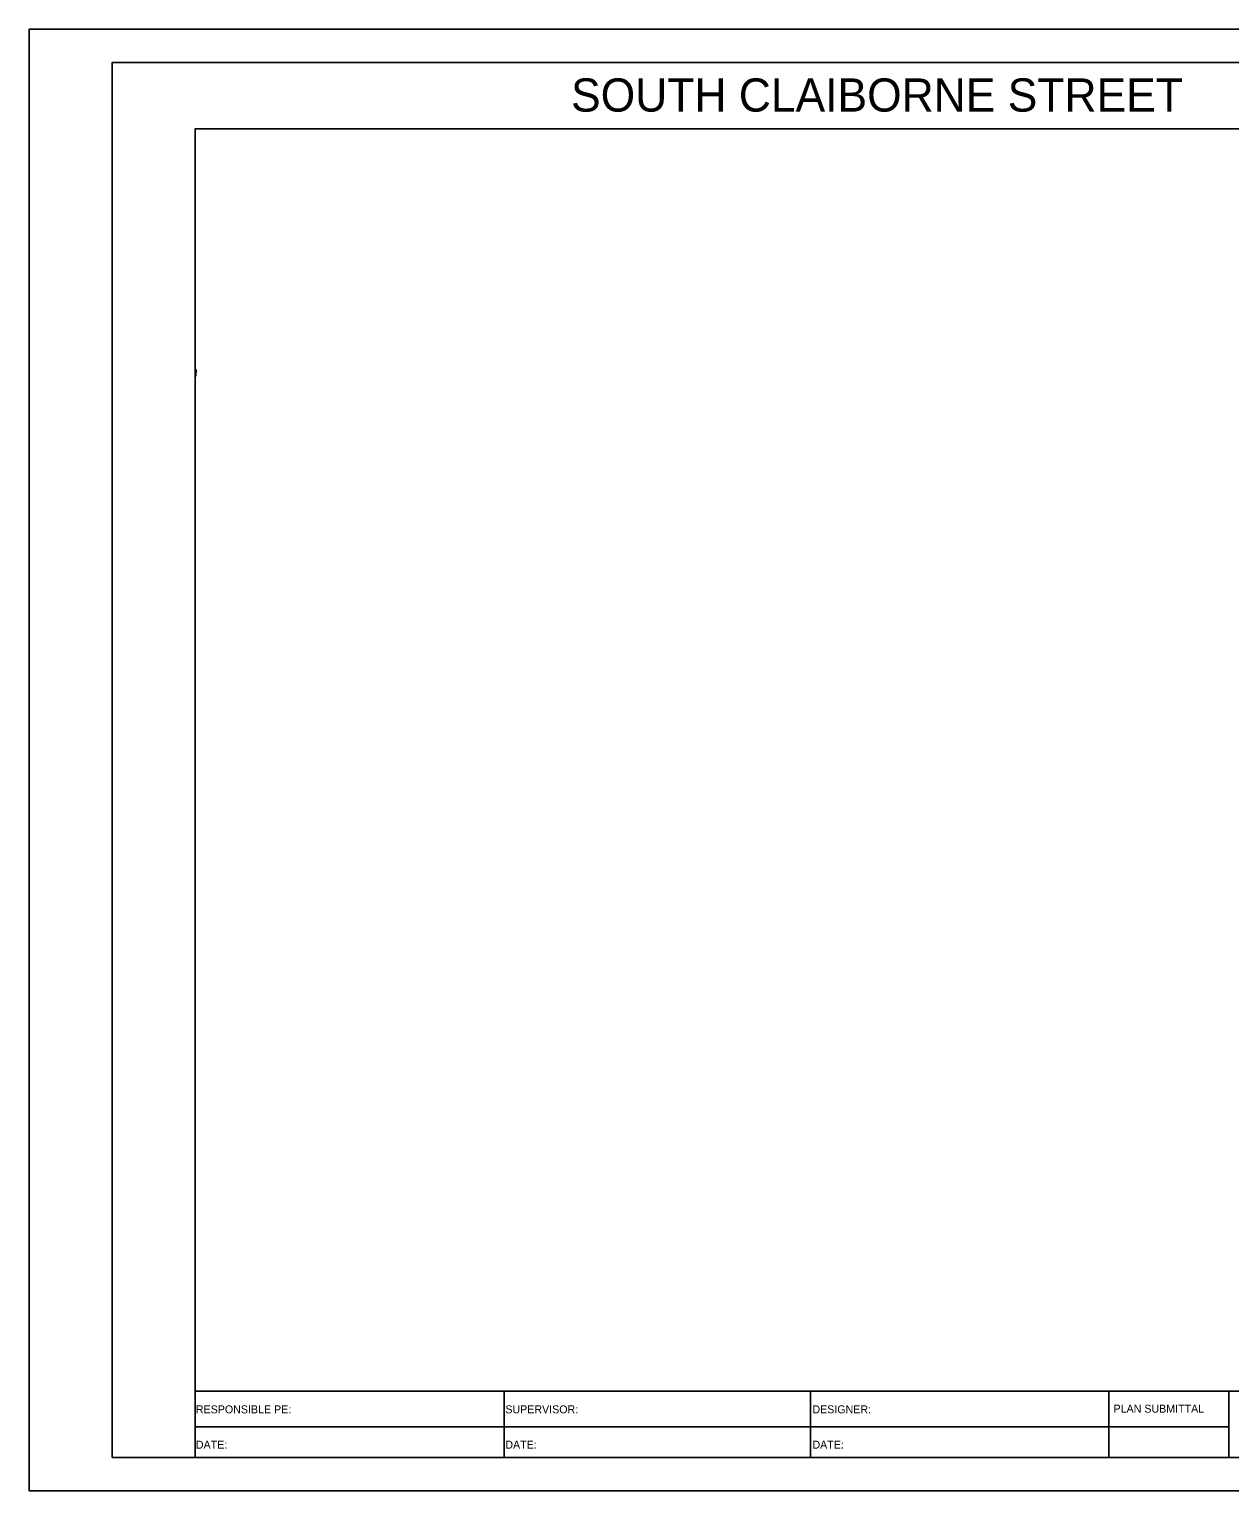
# Model space of a CAD drawing. Extents: x 1797478 to 1803816, y 246529 to 250952.
# Drawn here: x 1802116 to 1802296.8, y 250064.4 to 250284.4 of the extents above; entities that cross this region are included whole.
import ezdxf

# ---------------------------------------------------------------- set-up
doc = ezdxf.new("R2010")
doc.units = 0
for name, color, linetype in [('2', 7, 'Continuous'), ('ANNO-SHT', 7, 'Continuous'), ('ANNO-TXT', 7, 'Continuous'), ('AXIS', 7, 'Continuous'), ('DRAINAGE', 7, 'Continuous'), ('Level 1', 7, 'Continuous'), ('Level 62', 7, 'Continuous'), ('SHT-BDR', 7, 'Continuous'), ('SHT-BNDRY', 7, 'Continuous')]:
    doc.layers.add(name, color=color, linetype=linetype)

# ---------------------------------------------------------------- blocks, each defined once
blk = doc.blocks.new('SC47208')
at = {"layer": 'Level 1'}
blk.add_line((0, 0), (0, 0), dxfattribs=at)

msp = doc.modelspace()

# ---------------------------------------------------------------- linework, layer by layer
at = {"layer": '2'}
msp.add_lwpolyline([(1802141.12, 250233.21), (1802141.1, 250232.21)], dxfattribs=at)
msp.add_lwpolyline([(1802141.12, 250233.21), (1802141.1, 250232.21)], dxfattribs=at)
at = {"layer": 'AXIS'}
msp.add_line((1802141, 250189.42), (1802141, 250189.43), dxfattribs=at)
at = {"layer": 'Level 62'}
msp.add_lwpolyline([(1802116, 250064.42), (1802456, 250064.42), (1802456, 250284.42), (1802116, 250284.42)], close=True, dxfattribs=at)
at = {"layer": 'SHT-BDR'}
msp.add_lwpolyline([(1802141, 250079.43), (1802441, 250079.43), (1802441, 250269.43), (1802141, 250269.43)], close=True, dxfattribs=at)
at = {"layer": 'SHT-BNDRY'}
for p, q in [((1802141, 250069.42), (1802141, 250079.43)), ((1802187.52, 250079.43), (1802187.52, 250069.42)), ((1802233.67, 250069.42), (1802233.67, 250079.43)), ((1802278.59, 250069.42), (1802278.59, 250079.43)), ((1802296.63, 250069.42), (1802296.63, 250079.43)), ((1802141, 250074.03), (1802296.63, 250074.03))]:
    msp.add_line(p, q, dxfattribs=at)
msp.add_lwpolyline([(1802128.5, 250069.42), (1802451, 250069.42), (1802451, 250279.42), (1802128.5, 250279.42)], close=True, dxfattribs=at)

# ---------------------------------------------------------------- block references
at = {"layer": 'DRAINAGE', "xscale": 0.2, "yscale": 0.20000000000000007, "rotation": -116.41666666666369}
msp.add_blockref('SC47208', (1802291.32, 250274.62), dxfattribs=at)
msp.add_blockref('SC47208', (1802291.32, 250274.62), dxfattribs=at)

# ---------------------------------------------------------------- texts
at = {"layer": 'ANNO-SHT'}
msp.add_text('         SOUTH CLAIBORNE STREET         ', height=4.9995, rotation=360, dxfattribs=at).set_placement((1802180.88, 250272.02))
at = {"layer": 'ANNO-TXT'}
for s, p in [('RESPONSIBLE PE:', (1802141.1, 250076.08)), ('SUPERVISOR:', (1802187.7, 250076.08)), ('DESIGNER:', (1802233.94, 250076.08)), ('PLAN SUBMITTAL', (1802279.28, 250076.18)), ('DATE:', (1802141.1, 250070.76)), ('DATE:', (1802187.7, 250070.76)), ('DATE:', (1802233.94, 250070.76))]:
    msp.add_text(s, height=1.2, rotation=360, dxfattribs=at).set_placement(p)

doc.saveas('drawing.dxf')
